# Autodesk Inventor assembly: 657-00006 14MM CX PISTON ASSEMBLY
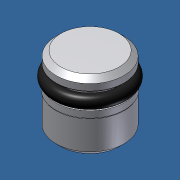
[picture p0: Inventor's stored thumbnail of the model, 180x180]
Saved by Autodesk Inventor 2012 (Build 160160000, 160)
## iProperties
Created: 2013-10
Part Number: 657-00006 14MM CX PISTON ASSEMBLY
Document SubType Name: Assembly
Designer: Admin
Author: Admin
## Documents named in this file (4)
- C:\Andys Backup Data\ANDY'S INVENTOR\INVENTOR LIBRARIES\PARTS LIBRARY\HYDRAULIC VERTICAL ADJUSTMENT\27.9001Telescoping Twin Leg System\SUBCOMPONENTS\CEx30 cylinder\657-00006 14MM CX PISTON ASSEMBLY.iam
- C:\Andys Backup Data\ANDY'S INVENTOR\INVENTOR LIBRARIES\PARTS LIBRARY\HYDRAULIC VERTICAL ADJUSTMENT\27.9001Telescoping Twin Leg System\SUBCOMPONENTS\CEx30 cylinder\H60 0003 PISTON BACKUP RINGS_660-00001A.ipt
- C:\Andys Backup Data\ANDY'S INVENTOR\INVENTOR LIBRARIES\PARTS LIBRARY\HYDRAULIC VERTICAL ADJUSTMENT\27.9001Telescoping Twin Leg System\SUBCOMPONENTS\CEx30 cylinder\H60-0004 O-RINGS_660-00004.ipt
- C:\Andys Backup Data\ANDY'S INVENTOR\INVENTOR LIBRARIES\PARTS LIBRARY\HYDRAULIC VERTICAL ADJUSTMENT\27.9001Telescoping Twin Leg System\SUBCOMPONENTS\CEx30 cylinder\657-00001 14MM CX CYLINDER PISTON.ipt
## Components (3 placed, 3 different names)
1. H60 0003 PISTON BACKUP RINGS_660-00001A:1
2. H60-0004 O-RINGS_660-00004:1
3. 657-00001 14MM CX CYLINDER PISTON:1
